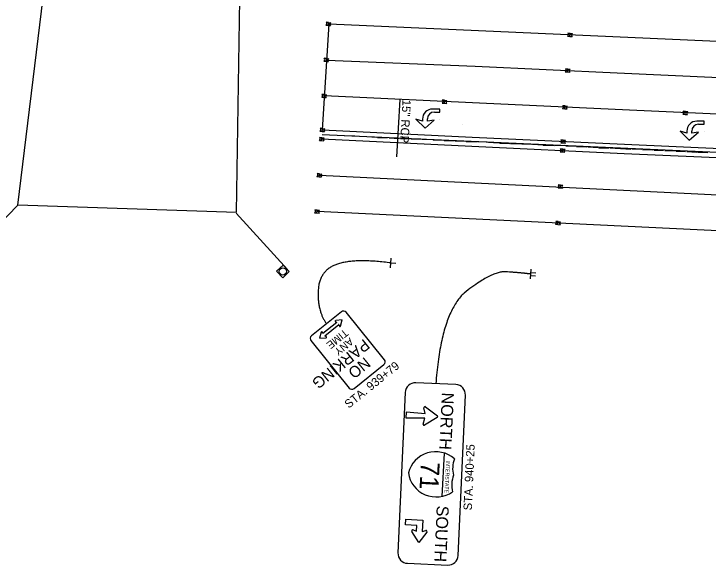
# Model space of a CAD drawing. Extents: x 1847379 to 1850904, y 217032 to 220169.
# Drawn here: x 1847990 to 1848220.4, y 218749.4 to 218932.5 of the extents above; entities that cross this region are included whole.
import ezdxf

# ---------------------------------------------------------------- set-up
doc = ezdxf.new("R2010")
doc.units = 0
for name, color, linetype in [('DR_X_Text', 7, 'Continuous'), ('PM_P_Cells', 7, 'Continuous'), ('PM_P_Channelizing_Line', 7, 'Continuous'), ('PM_P_CL_Double_Solid', 7, 'Continuous'), ('PM_P_Edge_Line', 7, 'Continuous'), ('PM_P_Lane_Line', 7, 'Continuous'), ('PM_P_Stop_Line', 7, 'Continuous'), ('RD_X_Bumper_Block', 7, 'Continuous'), ('SG_X_Wiring', 7, 'Continuous'), ('SN_X_Foundation', 7, 'Continuous'), ('SN_X_Public', 7, 'Continuous')]:
    doc.layers.add(name, color=color, linetype=linetype)

msp = doc.modelspace()

# ---------------------------------------------------------------- linework, layer by layer
at = {"layer": 'DR_X_Text'}
msp.add_line((1848117.13, 218884.97), (1848118.19, 218904.02), dxfattribs=at)
at = {"layer": 'PM_P_Cells'}
for p, q in [((1848093.6, 218928.72), (1848094.37, 218928.65)), ((1848093.6, 218928.72), (1848094.37, 218928.65)), ((1848094.45, 218929.62), (1848093.69, 218929.69)), ((1848093.69, 218929.69), (1848094.45, 218929.62)), ((1848094.37, 218928.65), (1848094.45, 218929.62)), ((1848094.37, 218928.65), (1848095.13, 218928.58)), ((1848094.45, 218929.62), (1848095.22, 218929.55)), ((1848174.66, 218925.98), (1848173.9, 218926.05)), ((1848173.9, 218926.05), (1848174.66, 218925.98)), ((1848174.58, 218925.01), (1848174.66, 218925.98)), ((1848174.66, 218925.98), (1848175.43, 218925.91)), ((1848173.81, 218925.08), (1848174.58, 218925.01)), ((1848173.81, 218925.08), (1848174.58, 218925.01)), ((1848174.58, 218925.01), (1848175.34, 218924.94)), ((1848092.89, 218916.76), (1848093.65, 218916.69)), ((1848092.89, 218916.76), (1848093.65, 218916.69)), ((1848093.74, 218917.66), (1848092.97, 218917.73)), ((1848092.97, 218917.73), (1848093.74, 218917.66)), ((1848093.65, 218916.69), (1848093.74, 218917.66)), ((1848093.65, 218916.69), (1848094.42, 218916.62)), ((1848093.74, 218917.66), (1848094.51, 218917.59)), ((1848173.9, 218914.16), (1848173.13, 218914.23)), ((1848173.13, 218914.23), (1848173.9, 218914.16)), ((1848173.81, 218913.19), (1848173.9, 218914.16)), ((1848173.9, 218914.16), (1848174.66, 218914.09)), ((1848173.04, 218913.26), (1848173.81, 218913.19)), ((1848173.04, 218913.26), (1848173.81, 218913.19)), ((1848173.81, 218913.19), (1848174.58, 218913.12)), ((1848092.17, 218904.79), (1848092.94, 218904.73)), ((1848092.17, 218904.79), (1848092.94, 218904.73)), ((1848093.01, 218905.71), (1848092.25, 218905.76)), ((1848092.25, 218905.76), (1848093.01, 218905.71)), ((1848092.94, 218904.73), (1848093.01, 218905.71)), ((1848092.94, 218904.73), (1848093.71, 218904.68)), ((1848093.01, 218905.71), (1848093.78, 218905.65)), ((1848132.14, 218902.88), (1848132.9, 218902.82)), ((1848132.14, 218902.88), (1848132.9, 218902.82)), ((1848132.97, 218903.8), (1848132.21, 218903.85)), ((1848132.21, 218903.85), (1848132.97, 218903.8)), ((1848132.9, 218902.82), (1848132.97, 218903.8)), ((1848132.9, 218902.82), (1848133.67, 218902.77)), ((1848132.97, 218903.8), (1848133.74, 218903.74)), ((1848131.43, 218900.88), (1848128.95, 218900.88)), ((1848131.43, 218899.88), (1848131.43, 218900.88)), ((1848172.1, 218901.01), (1848172.87, 218900.95)), ((1848172.1, 218901.01), (1848172.87, 218900.95)), ((1848172.94, 218901.93), (1848172.17, 218901.98)), ((1848172.17, 218901.98), (1848172.94, 218901.93)), ((1848172.87, 218900.95), (1848172.94, 218901.93)), ((1848172.87, 218900.95), (1848173.64, 218900.9)), ((1848172.94, 218901.93), (1848173.71, 218901.87)), ((1848212.9, 218900.08), (1848212.13, 218900.14)), ((1848212.13, 218900.14), (1848212.9, 218900.08)), ((1848212.83, 218899.11), (1848212.9, 218900.08)), ((1848212.9, 218900.08), (1848213.67, 218900.02)), ((1848129.57, 218899.88), (1848131.43, 218899.88)), ((1848212.06, 218899.16), (1848212.83, 218899.11)), ((1848212.06, 218899.16), (1848212.83, 218899.11)), ((1848212.83, 218899.11), (1848213.6, 218899.05)), ((1848123.43, 218897.55), (1848123.43, 218897.55)), ((1848125.67, 218896.88), (1848123.43, 218897.55)), ((1848123.43, 218897.55), (1848126.47, 218894.55)), ((1848125.67, 218897.55), (1848125.67, 218896.88)), ((1848126.47, 218894.55), (1848129.51, 218897.21)), ((1848127.27, 218896.88), (1848127.27, 218897.58)), ((1848129.51, 218897.21), (1848127.27, 218896.88)), ((1848131.43, 218897.55), (1848131.43, 218897.55)), ((1848219.15, 218896.87), (1848216.68, 218896.87)), ((1848217.29, 218895.87), (1848219.15, 218895.87)), ((1848219.15, 218895.87), (1848219.15, 218896.87)), ((1848091.59, 218893.52), (1848092.36, 218893.45)), ((1848091.59, 218893.52), (1848092.36, 218893.45)), ((1848092.45, 218894.43), (1848091.68, 218894.5)), ((1848091.68, 218894.5), (1848092.45, 218894.43)), ((1848092.36, 218893.45), (1848092.45, 218894.43)), ((1848092.36, 218893.45), (1848093.13, 218893.38)), ((1848092.45, 218894.43), (1848093.21, 218894.36)), ((1848211.15, 218893.53), (1848211.15, 218893.53)), ((1848213.39, 218892.87), (1848211.15, 218893.53)), ((1848211.15, 218893.53), (1848214.19, 218890.53)), ((1848213.39, 218893.53), (1848213.39, 218892.87)), ((1848214.19, 218890.53), (1848217.23, 218893.2)), ((1848214.99, 218892.87), (1848214.99, 218893.57)), ((1848217.23, 218893.2), (1848214.99, 218892.87)), ((1848219.15, 218893.53), (1848219.15, 218893.53)), ((1848092.25, 218891.37), (1848091.48, 218891.45)), ((1848091.48, 218891.45), (1848092.25, 218891.37)), ((1848092.16, 218890.4), (1848092.25, 218891.37)), ((1848092.25, 218891.37), (1848093.02, 218891.3)), ((1848092.31, 218892.47), (1848389.34, 218879.16)), ((1848091.39, 218890.47), (1848092.16, 218890.4)), ((1848091.39, 218890.47), (1848092.16, 218890.4)), ((1848092.16, 218890.4), (1848092.93, 218890.33)), ((1848171.51, 218889.7), (1848172.28, 218889.63)), ((1848171.51, 218889.7), (1848172.28, 218889.63)), ((1848172.37, 218890.6), (1848171.6, 218890.67)), ((1848171.6, 218890.67), (1848172.37, 218890.6)), ((1848172.28, 218889.63), (1848172.37, 218890.6)), ((1848172.28, 218889.63), (1848173.05, 218889.56)), ((1848172.37, 218890.6), (1848173.13, 218890.54)), ((1848171.32, 218886.71), (1848172.08, 218886.64)), ((1848171.32, 218886.71), (1848172.08, 218886.64)), ((1848172.17, 218887.61), (1848171.4, 218887.68)), ((1848171.4, 218887.68), (1848172.17, 218887.61)), ((1848172.08, 218886.64), (1848172.17, 218887.61)), ((1848172.08, 218886.64), (1848172.85, 218886.57)), ((1848172.17, 218887.61), (1848172.94, 218887.54)), ((1848091.47, 218879.36), (1848090.7, 218879.43)), ((1848090.7, 218879.43), (1848091.47, 218879.36)), ((1848091.38, 218878.39), (1848091.47, 218879.36)), ((1848091.47, 218879.36), (1848092.24, 218879.29)), ((1848090.61, 218878.46), (1848091.38, 218878.39)), ((1848090.61, 218878.46), (1848091.38, 218878.39)), ((1848091.38, 218878.39), (1848092.15, 218878.32)), ((1848170.62, 218874.75), (1848171.39, 218874.68)), ((1848170.62, 218874.75), (1848171.39, 218874.68)), ((1848171.48, 218875.65), (1848170.71, 218875.72)), ((1848170.71, 218875.72), (1848171.48, 218875.65)), ((1848171.39, 218874.68), (1848171.48, 218875.65)), ((1848171.39, 218874.68), (1848172.16, 218874.61)), ((1848171.48, 218875.65), (1848172.25, 218875.58)), ((1848089.83, 218866.44), (1848090.6, 218866.37)), ((1848089.83, 218866.44), (1848090.6, 218866.37)), ((1848090.69, 218867.35), (1848089.92, 218867.42)), ((1848089.92, 218867.42), (1848090.69, 218867.35)), ((1848090.6, 218866.37), (1848090.69, 218867.35)), ((1848090.6, 218866.37), (1848091.37, 218866.3)), ((1848090.69, 218867.35), (1848091.46, 218867.28)), ((1848170.67, 218863.51), (1848169.9, 218863.58)), ((1848169.9, 218863.58), (1848170.67, 218863.51)), ((1848170.58, 218862.54), (1848170.67, 218863.51)), ((1848170.67, 218863.51), (1848171.44, 218863.44)), ((1848169.81, 218862.61), (1848170.58, 218862.54)), ((1848169.81, 218862.61), (1848170.58, 218862.54)), ((1848170.58, 218862.54), (1848171.35, 218862.47))]:
    msp.add_line(p, q, dxfattribs=at)
for centre, radius, start, end in [((1848093.34, 218929.23), 0.576, 296.8063, 52.8586), ((1848093.34, 218929.23), 0.576, 296.8063, 52.8586), ((1848095.48, 218929.04), 0.576, 116.8063, 232.8586), ((1848173.55, 218925.59), 0.576, 296.8063, 52.8586), ((1848173.55, 218925.59), 0.576, 296.8063, 52.8586), ((1848175.69, 218925.4), 0.576, 116.8063, 232.8586), ((1848092.63, 218917.27), 0.576, 296.7517, 52.804), ((1848092.63, 218917.27), 0.576, 296.7517, 52.804), ((1848094.77, 218917.08), 0.576, 116.7517, 232.804), ((1848172.78, 218913.77), 0.576, 296.7517, 52.804), ((1848172.78, 218913.77), 0.576, 296.7517, 52.804), ((1848174.92, 218913.58), 0.576, 116.7517, 232.804), ((1848091.91, 218905.3), 0.576, 297.8101, 53.8624), ((1848091.91, 218905.3), 0.576, 297.8101, 53.8624), ((1848094.05, 218905.14), 0.576, 117.8101, 233.8624), ((1848131.87, 218903.39), 0.576, 297.8101, 53.8624), ((1848131.87, 218903.39), 0.576, 297.8101, 53.8624), ((1848134.01, 218903.23), 0.576, 117.8101, 233.8624), ((1848128.95, 218897.6), 3.28, 90, 180.9085), ((1848171.83, 218901.52), 0.576, 297.8101, 53.8624), ((1848171.83, 218901.52), 0.576, 297.8101, 53.8624), ((1848173.97, 218901.36), 0.576, 117.8101, 233.8624), ((1848211.79, 218899.67), 0.576, 297.8101, 53.8624), ((1848211.79, 218899.67), 0.576, 297.8101, 53.8624), ((1848213.94, 218899.51), 0.576, 117.8101, 233.8624), ((1848129.57, 218897.58), 2.3, 90, 180), ((1848216.68, 218893.58), 3.28, 90, 180.9085), ((1848217.29, 218893.57), 2.3, 90, 180), ((1848091.33, 218894.04), 0.576, 296.8063, 52.8586), ((1848091.33, 218894.04), 0.576, 296.8063, 52.8586), ((1848093.47, 218893.84), 0.576, 116.8063, 232.8586), ((1848091.13, 218890.99), 0.576, 296.7517, 52.804), ((1848091.13, 218890.99), 0.576, 296.7517, 52.804), ((1848093.28, 218890.79), 0.576, 116.7517, 232.804), ((1848171.25, 218890.22), 0.576, 296.8063, 52.8586), ((1848171.25, 218890.22), 0.576, 296.8063, 52.8586), ((1848173.39, 218890.02), 0.576, 116.8063, 232.8586), ((1848171.06, 218887.22), 0.576, 296.7517, 52.804), ((1848171.06, 218887.22), 0.576, 296.7517, 52.804), ((1848173.2, 218887.03), 0.576, 116.7517, 232.804), ((1848090.35, 218878.97), 0.576, 296.7517, 52.804), ((1848090.35, 218878.97), 0.576, 296.7517, 52.804), ((1848092.5, 218878.78), 0.576, 116.7517, 232.804), ((1848170.36, 218875.27), 0.576, 296.7517, 52.804), ((1848170.36, 218875.27), 0.576, 296.7517, 52.804), ((1848172.5, 218875.07), 0.576, 116.7517, 232.804), ((1848089.57, 218866.96), 0.576, 296.7517, 52.804), ((1848089.57, 218866.96), 0.576, 296.7517, 52.804), ((1848091.72, 218866.76), 0.576, 116.7517, 232.804), ((1848169.55, 218863.13), 0.576, 296.7517, 52.804), ((1848169.55, 218863.13), 0.576, 296.7517, 52.804), ((1848171.7, 218862.93), 0.576, 116.7517, 232.804)]:
    msp.add_arc(centre, radius, start, end, dxfattribs=at)
at = {"layer": 'PM_P_Channelizing_Line'}
msp.add_lwpolyline([(1848093.15, 218905.41), (1848144.56, 218902.95), (1848194.31, 218900.64), (1848245.43, 218898.29), (1848293.55, 218896.04), (1848343.05, 218893.8), (1848366.39, 218892.91)], dxfattribs=at)
at = {"layer": 'PM_P_CL_Double_Solid'}
for points in [[(1848092.4, 218893.94), (1848142.1, 218891.52), (1848192.74, 218889.17), (1848244.1, 218886.91), (1848292.7, 218884.63), (1848342.36, 218882.33), (1848384.68, 218880.9), (1848410.72, 218884.71), (1848435.62, 218888.6), (1848446.29, 218889.11), (1848496.28, 218886.67), (1848532.23, 218884.71), (1848581.34, 218881.58), (1848635.08, 218878.63), (1848691.11, 218875.57), (1848742.91, 218872.53), (1848797.97, 218869.41), (1848838.45, 218867.24), (1848839.96, 218866.49), (1848840.79, 218865.04), (1848840.57, 218862.3), (1848839.59, 218860.87), (1848837.82, 218860.26)], [(1848092.21, 218890.95), (1848141.96, 218888.52), (1848192.6, 218886.17), (1848243.96, 218883.92), (1848292.56, 218881.64), (1848342.24, 218879.33), (1848494.98, 218874.17)]]:
    msp.add_lwpolyline(points, dxfattribs=at)
at = {"layer": 'PM_P_Edge_Line'}
for p, q in [((1848468.73, 218912.18), (1848094.69, 218929.11)), ((1848324.68, 218855.5), (1848090.64, 218866.86))]:
    msp.add_line(p, q, dxfattribs=at)
at = {"layer": 'PM_P_Lane_Line'}
msp.add_line((1848091.42, 218878.87), (1848406.63, 218863.54), dxfattribs=at)
msp.add_lwpolyline([(1848093.91, 218917.13), (1848143.09, 218915.12), (1848190.28, 218912.91), (1848241.04, 218910.6), (1848292.87, 218908.29), (1848342.88, 218905.97), (1848396.54, 218903.43), (1848443.56, 218901.44), (1848492.82, 218898.95), (1848543.12, 218896.17), (1848588.69, 218893.34), (1848639.37, 218890.51), (1848690.94, 218887.73), (1848738.16, 218885.02), (1848789.62, 218882.19), (1848826.41, 218879.84)], dxfattribs=at)
at = {"layer": 'PM_P_Stop_Line'}
msp.add_line((1848092.4, 218893.94), (1848094.69, 218929.11), dxfattribs=at)
at = {"layer": 'RD_X_Bumper_Block'}
for points in [[(1848099.68, 218892.14), (1848103.16, 218891.94)], [(1848107.17, 218891.71), (1848110.45, 218891.55)], [(1848110.75, 218891.46), (1848114.07, 218891.48)], [(1848114.61, 218891.3), (1848117.93, 218891.1)], [(1848118.31, 218891.14), (1848121.48, 218891.06)], [(1848121.78, 218891.02), (1848125.07, 218890.97)], [(1848125.51, 218890.86), (1848128.99, 218890.73)], [(1848129.15, 218890.64), (1848132.5, 218890.57)], [(1848132.85, 218890.48), (1848136.15, 218890.37)], [(1848136.53, 218890.37), (1848139.97, 218890.19)], [(1848140.08, 218890.13), (1848143.54, 218890.04)], [(1848143.87, 218890.1), (1848147.07, 218889.98)], [(1848147.52, 218889.87), (1848150.84, 218889.66)], [(1848151.25, 218889.59), (1848154.58, 218889.44)], [(1848154.86, 218889.43), (1848158.19, 218889.33)], [(1848158.5, 218889.32), (1848161.83, 218889.24)], [(1848162.18, 218889.2), (1848165.57, 218889.03)], [(1848165.74, 218888.94), (1848169.2, 218888.87)], [(1848169.44, 218888.81), (1848172.85, 218888.85)], [(1848173.2, 218888.68), (1848176.62, 218888.66)], [(1848176.79, 218888.42), (1848180.17, 218888.36)], [(1848180.5, 218888.31), (1848183.9, 218888.16)], [(1848184.16, 218888.03), (1848187.54, 218887.95)], [(1848187.84, 218887.95), (1848191.32, 218887.73)], [(1848191.45, 218887.79), (1848194.8, 218887.58)], [(1848195.14, 218887.66), (1848198.47, 218887.56)], [(1848198.71, 218887.44), (1848202.05, 218887.38)], [(1848202.42, 218887.23), (1848205.64, 218887.21)], [(1848206.09, 218887.06), (1848209.41, 218887.06)], [(1848209.72, 218886.92), (1848212.98, 218886.79)], [(1848213.34, 218886.81), (1848216.67, 218886.56)], [(1848216.97, 218886.58), (1848220.34, 218886.46)]]:
    msp.add_lwpolyline(points, dxfattribs=at)
at = {"layer": 'SG_X_Wiring'}
for p, q in [((1847991.33, 218868.98), (1847999.88, 218939.03)), ((1848063.94, 218866.48), (1848065.02, 218937.49)), ((1847991.33, 218868.98), (1847969.6, 218846.82)), ((1848063.94, 218866.48), (1847991.33, 218868.98)), ((1848063.83, 218866.28), (1848080.85, 218847.61))]:
    msp.add_line(p, q, dxfattribs=at)
at = {"layer": 'SN_X_Foundation'}
msp.add_lwpolyline([(1848079.25, 218844.85), (1848081.41, 218846.93), (1848079.33, 218849.09), (1848077.17, 218847.01)], close=True, dxfattribs=at)
msp.add_circle((1848079.29, 218846.97), 1.2, dxfattribs=at)
at = {"layer": 'SN_X_Public'}
for p, q in [((1848138.85, 218895.81), (1848138.85, 218895.81)), ((1848115.04, 218848.18), (1848115.28, 218851.37)), ((1848115.16, 218849.77), (1848116.76, 218849.65)), ((1848161.52, 218844.49), (1848161.71, 218847.68)), ((1848161.59, 218845.61), (1848163.19, 218845.51)), ((1848161.62, 218846.09), (1848161.62, 218846.09)), ((1848161.65, 218846.56), (1848163.24, 218846.47)), ((1848098.97, 218830.85), (1848096.81, 218830.71)), ((1848098.37, 218828.77), (1848098.97, 218830.85)), ((1848093.18, 218825.59), (1848097.81, 218829.32)), ((1848096.72, 218830.38), (1848097.22, 218830.05)), ((1848097.81, 218829.32), (1848097.8, 218829.31)), ((1848097.81, 218829.32), (1848098.03, 218828.76)), ((1848092.03, 218826.85), (1848091.43, 218824.77)), ((1848092.59, 218826.31), (1848092.37, 218826.87)), ((1848095.2, 218827.81), (1848095.2, 218827.81)), ((1848091.43, 218824.77), (1848093.59, 218824.92)), ((1848093.18, 218825.58), (1848093.18, 218825.59)), ((1848093.67, 218825.25), (1848093.18, 218825.58)), ((1848126.47, 218799.76), (1848126.13, 218801.7)), ((1848126.66, 218802.03), (1848130.56, 218799.03)), ((1848120.23, 218798.27), (1848120.34, 218800.34)), ((1848120.34, 218800.34), (1848126.47, 218799.76)), ((1848125.94, 218799.03), (1848125.94, 218799.03)), ((1848126.38, 218798.2), (1848120.23, 218798.27)), ((1848125.84, 218796.3), (1848126.38, 218798.2)), ((1848130.53, 218798.48), (1848126.34, 218795.92)), ((1848132.8, 218786.67), (1848132.02, 218772.26)), ((1848128.69, 218779.72), (1848128.69, 218779.72)), ((1848120.02, 218762.8), (1848120.12, 218764.68)), ((1848120.12, 218764.68), (1848125.74, 218764.38)), ((1848125.74, 218764.38), (1848125.54, 218760.62)), ((1848123.77, 218762.6), (1848120.02, 218762.8)), ((1848123.66, 218760.72), (1848123.77, 218762.6)), ((1848124.4, 218756.94), (1848122.11, 218760.6)), ((1848122.55, 218761.14), (1848123.66, 218760.72)), ((1848124.25, 218761.57), (1848124.25, 218761.57)), ((1848127.07, 218760.34), (1848124.4, 218756.94)), ((1848125.54, 218760.62), (1848126.69, 218760.92))]:
    msp.add_line(p, q, dxfattribs=at)
for points in [[(1848098.71, 218833.57), (1848088.78, 218825.57)], [(1848113, 218817.63), (1848100.29, 218833.4)], [(1848097.22, 218830.05), (1848092.59, 218826.32)], [(1848088.61, 218823.99), (1848101.32, 218808.22)], [(1848102.9, 218808.05), (1848112.83, 218816.05)], [(1848136.7, 218809.39), (1848123.38, 218809.99)], [(1848119.9, 218806.81), (1848117.49, 218753.53)], [(1848137.47, 218752.63), (1848139.88, 218805.91)], [(1848120.67, 218750.05), (1848133.99, 218749.45)]]:
    msp.add_lwpolyline(points, dxfattribs=at)
for centre, radius, start, end in [((1848099.42, 218832.69), 1.12, 38.8676, 128.8676), ((1848096.82, 218830.53), 0.182, 93.7884, 236.5054), ((1848098.2, 218828.82), 0.182, 201.2298, 343.9469), ((1848092.2, 218826.8), 0.182, 21.2298, 163.9469), ((1848089.49, 218824.69), 1.12, 128.8676, 218.8676), ((1848093.57, 218825.1), 0.182, 273.7884, 56.5054), ((1848112.13, 218816.93), 1.12, 308.8676, 38.8676), ((1848102.2, 218808.93), 1.12, 218.8676, 308.8676), ((1848123.23, 218806.66), 3.33, 87.4125, 177.4125), ((1848136.55, 218806.06), 3.33, 357.4125, 87.4125), ((1848126.46, 218801.76), 0.338, 52.4325, 189.9058), ((1848130.35, 218798.77), 0.338, 302.836, 51.0233), ((1848126.16, 218796.21), 0.338, 163.9534, 301.4267), ((1848130.01, 218777.72), 9.38, 48.5986, 165.3926), ((1848145.02, 218781.53), 9.38, 159.9387, 193.9205), ((1848130.21, 218781.46), 9.38, 188.4666, 305.2606), ((1848144.73, 218776.06), 9.38, 159.9387, 193.9205), ((1848122.42, 218760.8), 0.365, 69.2918, 212.0089), ((1848126.79, 218760.56), 0.365, 321.8504, 104.5674), ((1848120.82, 218753.38), 3.33, 177.4125, 267.4125), ((1848134.14, 218752.78), 3.33, 267.4125, 357.4125)]:
    msp.add_arc(centre, radius, start, end, dxfattribs=at)
for points in [[(1848115.16, 218849.77), (1848103.3, 218851.37), (1848091.4, 218847.39), (1848090.63, 218834.03), (1848093.75, 218829.57)], [(1848161.62, 218846.09), (1848156.65, 218846.69), (1848148.92, 218846.96), (1848131.89, 218834.15), (1848130.04, 218809.69)]]:
    msp.add_open_spline(points, degree=2, dxfattribs=at)

# ---------------------------------------------------------------- texts
at = {"layer": 'DR_X_Text'}
msp.add_text('15" RCP', height=2.8, rotation=266.8346, dxfattribs=at).set_placement((1848119.01, 218904.04))
at = {"layer": 'SN_X_Public'}
for s, height, rotation, p in [('TIME', 2.5, 218.8676, (1848099.74, 218827.98)), ('PARKING', 3.75, 218.8676, (1848106.17, 218824.73)), ('ANY', 2.5, 218.8676, (1848101.45, 218825.14)), ('NO', 3.75, 218.8676, (1848106.42, 218818.71)), ('STA. 939+79', 2.8, 38.8676, (1848101.14, 218801.34)), ('NORTH', 4, 267.4125, (1848132.08, 218806.81)), ('STA. 940+25', 2.8, 87.4125, (1848142.01, 218767.59)), ('71', 6.25, 266.9296, (1848125.14, 218783.91)), ('INTERSTATE', 1.25, 266.9296, (1848133.52, 218784.14)), ('SOUTH', 4, 267.4125, (1848130.38, 218769.26))]:
    msp.add_text(s, height=height, rotation=rotation, dxfattribs=at).set_placement(p)

doc.saveas('drawing.dxf')
